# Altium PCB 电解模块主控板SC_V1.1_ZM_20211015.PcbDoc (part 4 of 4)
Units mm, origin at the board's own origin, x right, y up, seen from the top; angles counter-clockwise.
Board outline 150.25 x 100.26 mm, 2 copper layers (Top Layer, Bottom Layer); 222 components, 167 nets, 677 pads, 2045 vias.
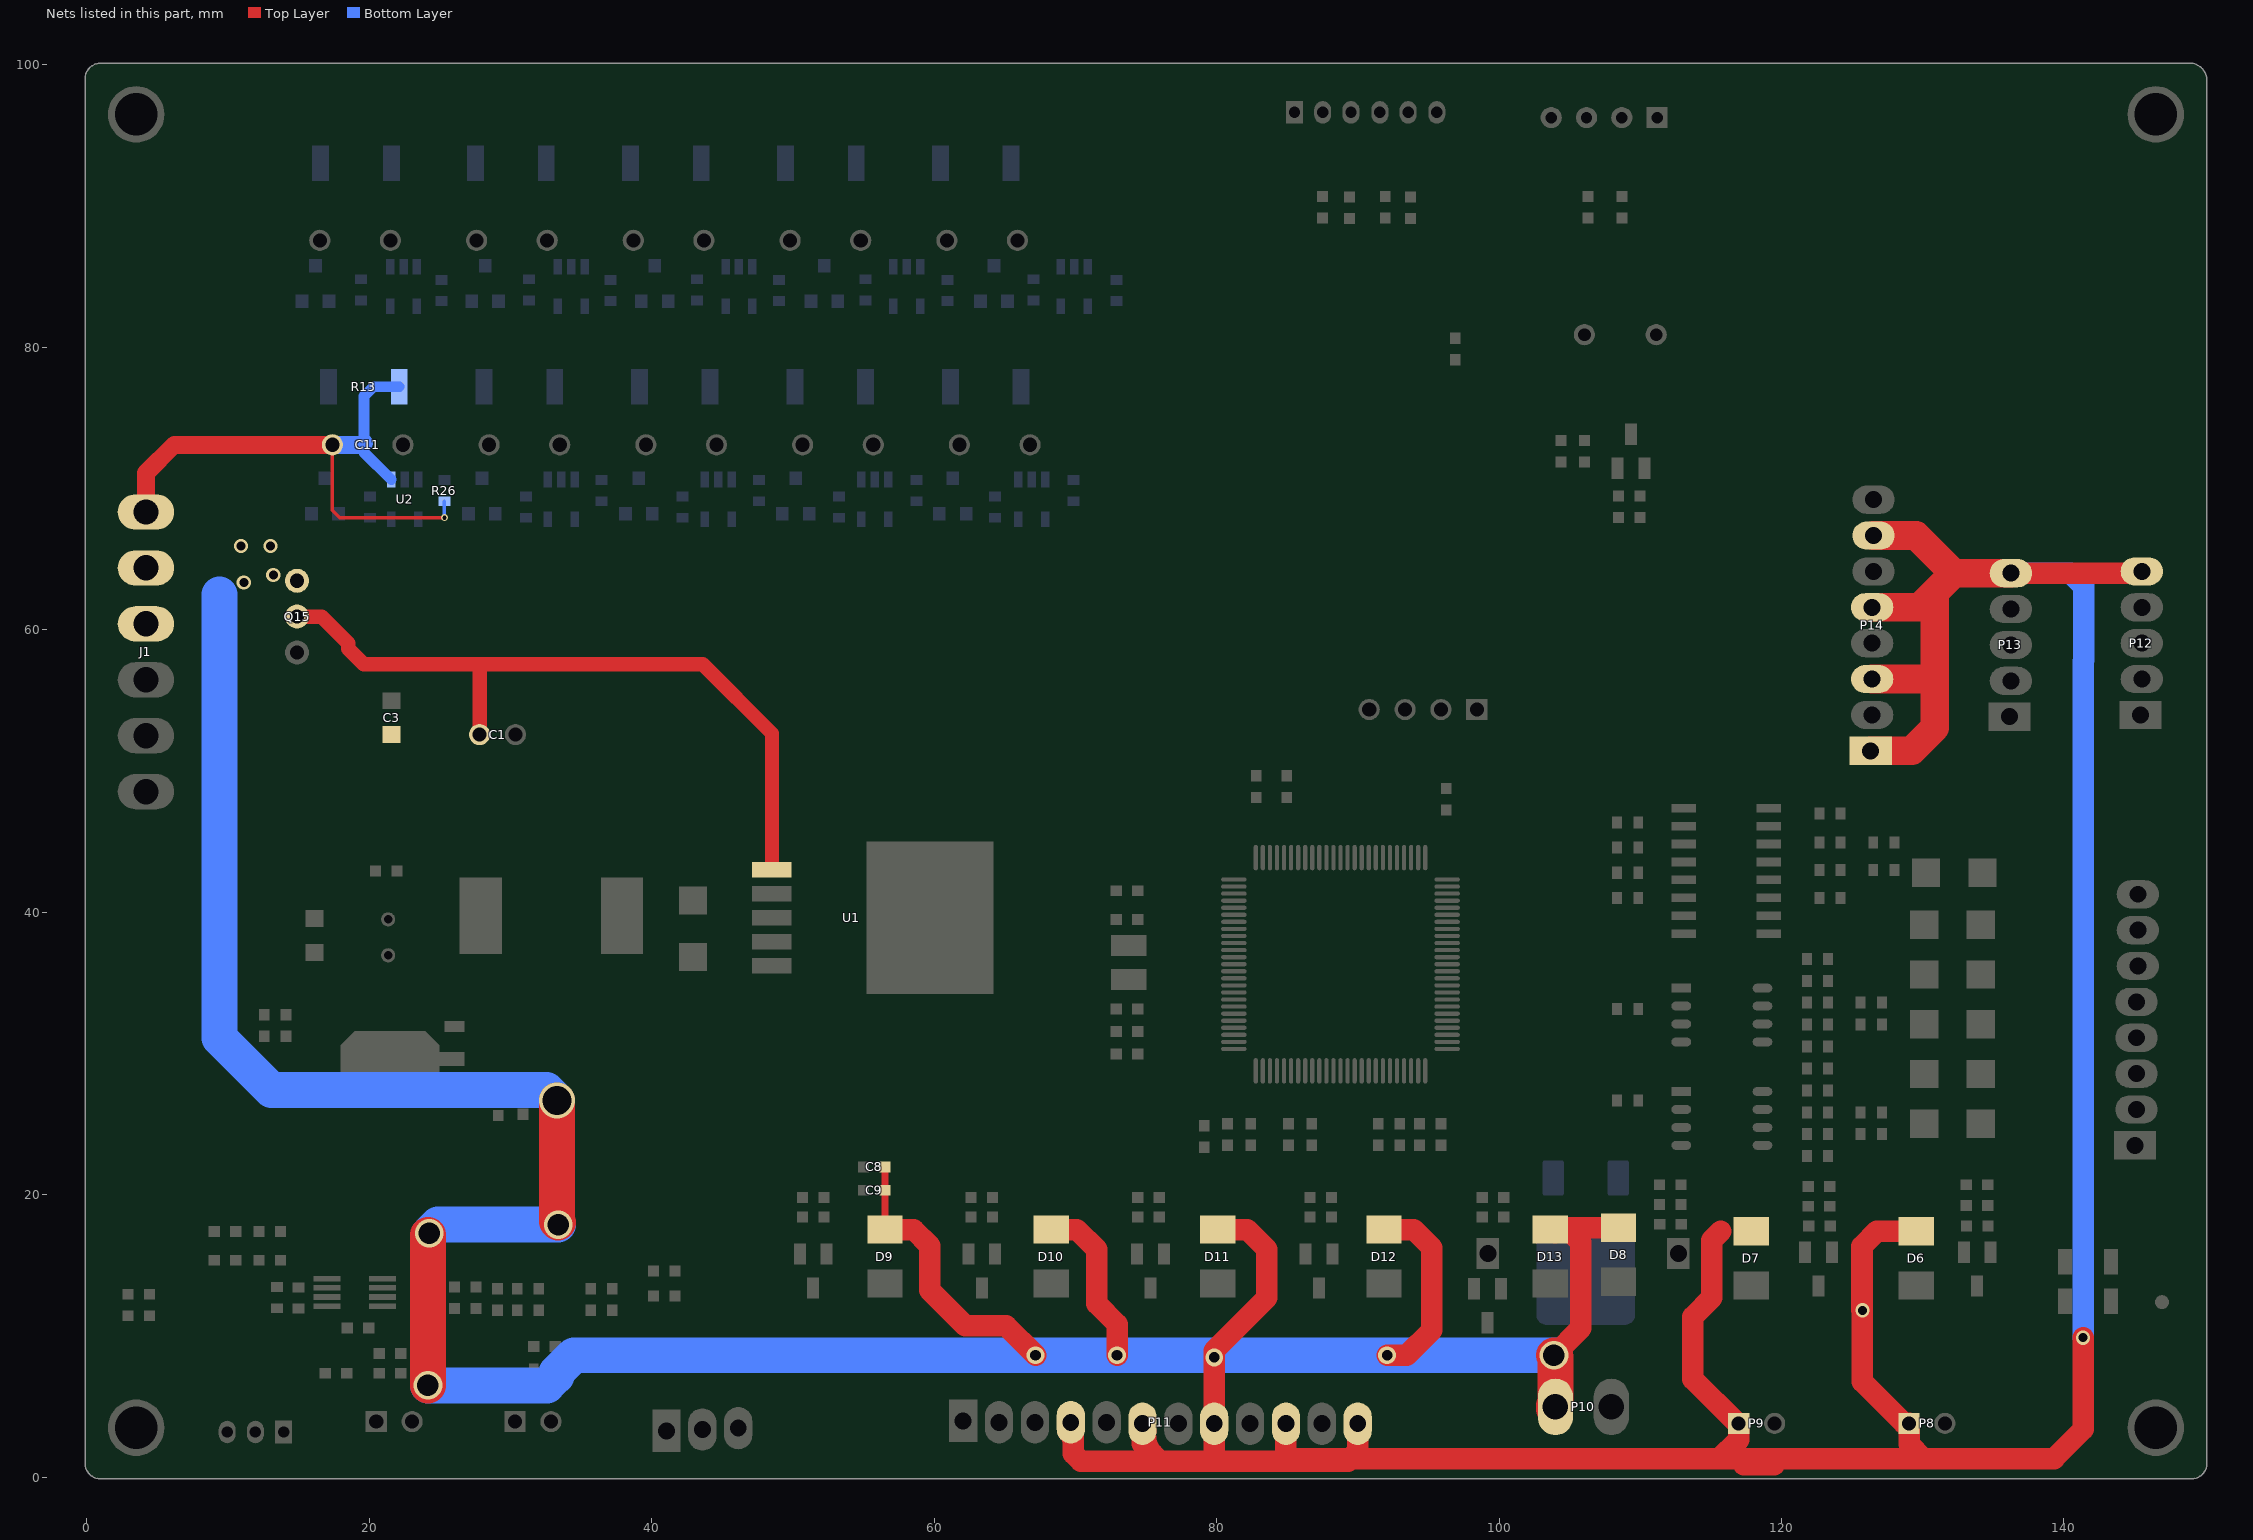
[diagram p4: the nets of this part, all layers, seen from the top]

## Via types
v1: diameter 0.762, hole 0.508, Top Layer to Bottom Layer, tented both sides, 1838 vias
v2: diameter 0.508, hole 0.305, Top Layer to Bottom Layer, tented both sides, 135 vias
v3: diameter 1.016, hole 0.635, Top Layer to Bottom Layer, tented both sides, 63 vias
v4: diameter 2.032, hole 1.524, Top Layer to Bottom Layer, tented both sides, 4 vias
v5: diameter 1.27, hole 0.762, Top Layer to Bottom Layer, tented both sides, 4 vias
v6: diameter 2.54, hole 2.032, Top Layer to Bottom Layer, tented both sides, 1 vias

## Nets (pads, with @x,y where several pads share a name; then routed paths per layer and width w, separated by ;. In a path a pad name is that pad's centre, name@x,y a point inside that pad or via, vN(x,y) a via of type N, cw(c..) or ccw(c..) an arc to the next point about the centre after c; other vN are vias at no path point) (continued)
VDD12V: C8.2 C9.2 C11.1 D6.2 D7.2 D8.2 D9.2 D10.2 D11.2 D12.2 D13.2 J1.4 J1.5 J1.6 P8.1 P9.1 P10.1 P11.4 P11.6 P11.8 P11.10 P11.12 P12.5 P13.5 P14.1 P14.3 P14.5 P14.7 Q15.3 R13.1 R26.1 U2.1 | length 544.3
  Top Layer w0.254: C11.1@17.388,73.101 17.388,68.464 17.907,67.945 v2(25.324,67.945)
  Top Layer w0.508: D9.2@56.515,17.536 C9.2@56.515,20.32 C8.2@56.515,21.971
  Top Layer w1.27: J1.6@4.191,68.343 4.191,71.095 6.198,73.101 C11.1@17.388,73.101
  Top Layer w1.524: v4(33.376,17.882) v4@33.376,18.034 ; D9.2@56.515,17.536 58.537,17.536 59.69,16.383 59.69,13.233 62.192,10.731 65.087,10.731 v5(67.183,8.636) ; D10.2@68.294,17.536 70.094,17.536 71.501,16.129 71.501,12.294 72.949,10.846 v5(72.949,8.636) ; P11.4@69.504,3.22 cw(c68.668,2.384) 69.85,2.384 ; P11.4@69.672,3.888 69.85,3.71 69.85,1.676 70.383,1.143 75.971,1.143 ; P11.6@74.752,3.788 74.752,2.362 75.971,1.143 ; P11.6@74.987,3.248 ccw(c76.833,2.931) 75.509,1.606 ; v5@79.832,8.966 P11.8@79.832,3.788 79.832,1.219 79.908,1.143 ; v5(79.833,8.484) 79.833,8.967 83.566,12.7 83.566,16.129 82.159,17.536 D11.2@80.073,17.536 ; P11.10@84.912,3.788 84.912,1.295 89.459,1.295 ; P11.12@89.992,3.788 89.992,1.829 89.459,1.295 ; D12.2@91.853,17.536 93.97,17.536 95.25,16.256 95.25,10.414 93.472,8.636 v5(92.075,8.636) ; v4(103.886,8.636) 105.796,10.546 105.796,16.632 104.892,17.536 D13.2@103.632,17.536 103.759,17.663 D8.2@108.458,17.663 ; D13.2@103.973,17.316 cw(c104.471,16.105) 105.397,17.031 ; 115.707,17.409 115.062,16.764 115.062,12.7 113.728,11.367 113.728,6.947 116.865,3.81 P9.1@116.967,3.81 116.967,2.667 115.595,1.295 ; 117.323,0.889 119.472,0.889 ; v3@125.698,11.811 125.698,16.351 126.756,17.409 D6.2@129.54,17.409 ; v3(125.73,11.811) 125.73,6.751 128.671,3.81 P8.1@129.032,3.81 129.032,2.337 130.048,1.321 131.42,1.321 ; P13.5@136.244,64.008 145.388,64.008 P12.5@145.515,64.135 ; v3(141.351,9.881) 141.351,3.378 139.294,1.321 131.42,1.321 ; 75.971,1.143 79.908,1.143 ; 79.908,1.143 89.306,1.143 89.459,1.295 ; 89.459,1.295 115.595,1.295 ; 115.595,1.295 131.394,1.295 131.42,1.321
  Top Layer w2.032: P14.1@126.316,51.435 129.235,51.435 130.861,53.061 130.861,56.769 ; P14.3@126.416,56.515 130.607,56.515 130.861,56.769 ; P14.5@126.416,61.595 129.794,61.595 130.861,62.662 ; P14.7@126.516,66.675 129.54,66.675 132.207,64.008 ; P13.5@136.244,64.008 132.207,64.008 ; 130.861,56.769 130.861,62.662 ; 130.861,62.662 132.207,64.008
  Top Layer w2.54: v4(24.155,6.502) v4@24.155,17.17 ; v6(33.299,26.67) 33.299,18.11 v4@33.376,18.034 ; P10.1@103.886,4.826 103.886,5.082 P10.1@103.99,4.978 103.99,8.532 v4(103.886,8.636)
  Bottom Layer w0.254: v2(25.324,67.945) R26.1@25.324,69.105
  Bottom Layer w0.762: U2.1@21.554,70.644 19.634,72.564 19.634,73.228 19.634,76.556 20.295,77.216 R13.1@22.123,77.216
  Bottom Layer w1.27: C11.1@17.388,73.101 19.507,73.101 19.634,73.228
  Bottom Layer w1.524: P13.5@136.244,64.008 140.487,64.008 141.402,63.094 141.402,57.836 141.351,57.785 v3(141.351,9.881)
  Bottom Layer w2.54: 9.398,62.509 9.398,31.09 13.081,27.407 32.563,27.407 v6(33.299,26.67) ; v4(24.155,6.502) 32.582,6.502 33.249,7.169 33.249,7.4 34.485,8.636 v5(67.183,8.636) v5(72.949,8.636) v5(92.075,8.636) v4(103.886,8.636) ; v4(24.257,17.272) 24.867,17.882 v4(33.376,17.882)
  other v3: 11.125,63.348 13.208,63.881 10.922,65.938 13.005,65.938
VDD12V1: C1.1 C3.2 Q15.2 U1.1 | length 52
  Top Layer w1.016: Q15.2@14.884,60.935 16.637,60.935 18.517,59.055 18.517,58.654 19.615,57.556 27.61,57.556 ; C1.1@27.813,52.578 27.813,57.353 27.61,57.556 ; U1.1@48.514,43.024 48.514,52.654 43.612,57.556 27.61,57.556
pads on no net: P5.5 P5.6 P12.1 P13.1 Q8.4 Q8.5 U2.4 U3.7 U3.9 U4.4 U5.4 U6.4 U7.4 U10.7 U10.8 U10.9 U10.15 U10.16 U10.17 U10.18 U10.37 U10.55 U10.60 U10.67 U10.77 U10.84 U10.96 U10.97 U10.98 U12.4 U13.4 U14.4 U15.4 U16.4
copper on no net: | length 30.8
  Top Layer w0.254: v2(82.169,96.393) 82.169,79.121 82.55,78.74 84.709,78.74
  Top Layer w0.508: 84.709,82.55 84.709,80.264 86.614,80.264 87.376,80.264 88.209,79.431 89.465,79.431 ; 89.465,80.091 89.465,80.731 89.465,82.48 89.789,82.804 90.424,82.804

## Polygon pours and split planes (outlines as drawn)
GND on Bottom Layer "Top Layer-No Net" (solid, remove dead copper, pour order 12): -3.937,105.156 154.305,105.156 155.194,106.045 157.099,104.14 157.099,-2.413 120.777,-2.413 117.348,-5.842 113.538,-2.032 -4.953,-2.032 -4.953,106.045 -4.699,106.299
GND on Top Layer "Top Layer-No Net" (solid, remove dead copper, pour order 10): -21.793,109.093 -14.282,101.582 154.102,101.582 154.102,-0.762 -10.109,-0.762 -10.109,101.582

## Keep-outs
Keep-Out Layer:
  circle w0.127: c3.475,3.475 r3
  circle w0.127: c3.525,96.566 r3
  circle w0.127: c146.553,96.515 r3
  circle w0.127: c146.451,3.525 r3
  lines w0.254: 0.746,100 148.746,100 ; 1,100 ccw(c1,99) 0,99 0,1 ccw(c1,1) 1,0 149,0 ccw(c149,1) 150,1 150,99 ccw(c148.859,98.859) 148.717,100
Mechanical 1:
  lines w0.254: 0.762,100 148.762,100 ; 1.016,100 ccw(c1.016,99) 0.016,99 0.016,1 ccw(c1.016,1) 1.016,0 149.016,0 ccw(c149.016,1) 150.016,1 150.016,99 ccw(c148.875,98.859) 148.733,100

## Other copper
Top Layer:
  rectangle net NetC32_2: 144.094,1.295 148.692,16.637
  rectangle net NetC32_2: 142.799,11.278 148.184,16.637
  rectangle net GND: 52.578,36.703 66.675,42.799
  rectangle net GND: 57.785,33.909 61.976,45.466
  rectangle net GND: 13.183,57.963 16.743,58.776
  rectangle net GND: 14.478,57.302 15.367,59.334
  rectangle net GND: 1.422,56.032 7.315,57.15
  rectangle net GND: 3.226,46.584 4.826,58.242
  rectangle net GND: 1.27,52.095 7.163,52.984
  rectangle net GND: 1.524,48.133 7.264,49.2
  region net VDD12V1: 24.511,53.34 25.273,54.102 29.083,54.102 29.083,51.943 28.321,51.181 20.447,51.181 20.193,51.435 20.193,52.959 20.574,53.34
  region net VDD12V: 2.794,70.104 9.271,70.104 12.776,66.599 15.926,66.599 15.926,62.509 12.979,62.509 9.271,58.801 2.794,58.801 1.905,59.69 1.905,69.215
Bottom Layer:
  rectangle net GND: 13.335,58.064 16.383,58.776
  region net NetD8_1: 103.911,17.932 103.937,17.958 109.931,17.958 110.388,17.501 110.388,4.674 108.458,2.743 106.705,2.743 106.248,3.2 106.248,9.5 105.054,10.693 103.022,10.693 102.184,11.532 102.184,17.501 102.616,17.932
  region net VDD12V: 2.794,70.104 9.271,70.104 12.776,66.599 15.977,66.599 15.977,62.535 13.005,62.535 9.271,58.801 2.794,58.801 1.905,59.69 1.905,69.215

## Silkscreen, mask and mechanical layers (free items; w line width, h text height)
Top Overlay:
  circle w0.5: c3.5,3.5 r2.5
  circle w0.5: c3.5,96.5 r2.5
  circle w0.5: c146.5,96.5 r2.5
  circle w0.5: c146.5,3.5 r2.5
  text "uart3" at 79.248,95.631 h2.03
  text "uart1" at 115.062,94.234 h2.03
  text "+" at 10.541,64.135 h2.03
  text "12V" at 130.454,63.856 h1.27
  text "GND" at 130.683,61.112 h1.27
  text "+" at 10.795,60.198 h2.03
  text "AOPWMG_V1.4 20220308" at 44.348,59.792 h2.54
  text "A" at 131.648,59.106 h1.27
  text "-" at 11.684,56.515 h2.03 r90
  text "B" at 131.623,56.21 h1.27
  text "-" at 11.557,52.832 h2.03 r90
  text "-" at 11.557,49.276 h2.03 r90
  text "A" at 140.157,40.919 h1.27
  text "B" at 140.157,38.405 h1.27
  text "A" at 140.157,35.89 h1.27
  text "B" at 140.157,33.376 h1.27
  text "A" at 140.157,30.861 h1.27
  text "B" at 140.157,28.346 h1.27
  text "A" at 140.157,25.832 h1.27
  text "B" at 140.157,23.317 h1.27
  text "泵1" at 106.858,9.423 h1.27
  text "G" at 109.322,9.093 h1.02
  text "24V" at 99.314,9.042 h1.02
  text "高压开关" at 60.833,7.992 h1.27
  text "阀1" at 67.539,8.001 h1.27
  text "阀2" at 72.517,8.001 h1.27
  text "阀3" at 77.876,8.001 h1.27
  text "阀4" at 82.829,8.001 h1.27
  text "阀5" at 88.417,8.001 h1.27
  text "5V" at 45.695,7.925 h1.02
  text "流量计" at 41.224,7.823 h1.27
  text "G" at 39.522,7.772 h1.02
  text "泵3" at 129.718,6.934 h1.27
  text "泵2" at 116.789,6.807 h1.27
  text "G" at 133.325,6.756 h1.02
  text "24V" at 125.095,6.629 h1.02
  text "24V" at 113.182,6.604 h1.02
  text "G" at 119.583,6.401 h1.02
  text "水位开关" at 8.001,5.817 h1.27
  text "原水TDS" at 35.992,5.766 h1.27 r270
  text "G" at 14.199,5.512 h1.02
  text "进水TDS" at 26.162,5.359 h1.27 r270
Top Solder:
  lines w2.54: 24.155,6.502 24.155,17.17 ; 33.376,18.034 33.401,26.772
Bottom Solder:
  lines w2.54: 9.373,62.509 9.373,31.09 13.056,27.407 32.537,27.407 ; 24.155,6.502 32.582,6.502 ; 24.867,17.882 33.376,17.882 ; 33.206,7.4 34.442,8.636 67.141,8.636 ; 67.183,8.636 72.949,8.636 103.886,8.636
